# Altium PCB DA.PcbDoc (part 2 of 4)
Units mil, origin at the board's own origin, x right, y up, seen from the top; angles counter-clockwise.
Board outline 6588.03 x 5423.03 mil, 4 copper layers (Top Layer, GND, VCC, Bottom Layer); 506 components, 345 nets, 1676 pads, 350 vias.
Unrouted connection lines stored in the file: 30.
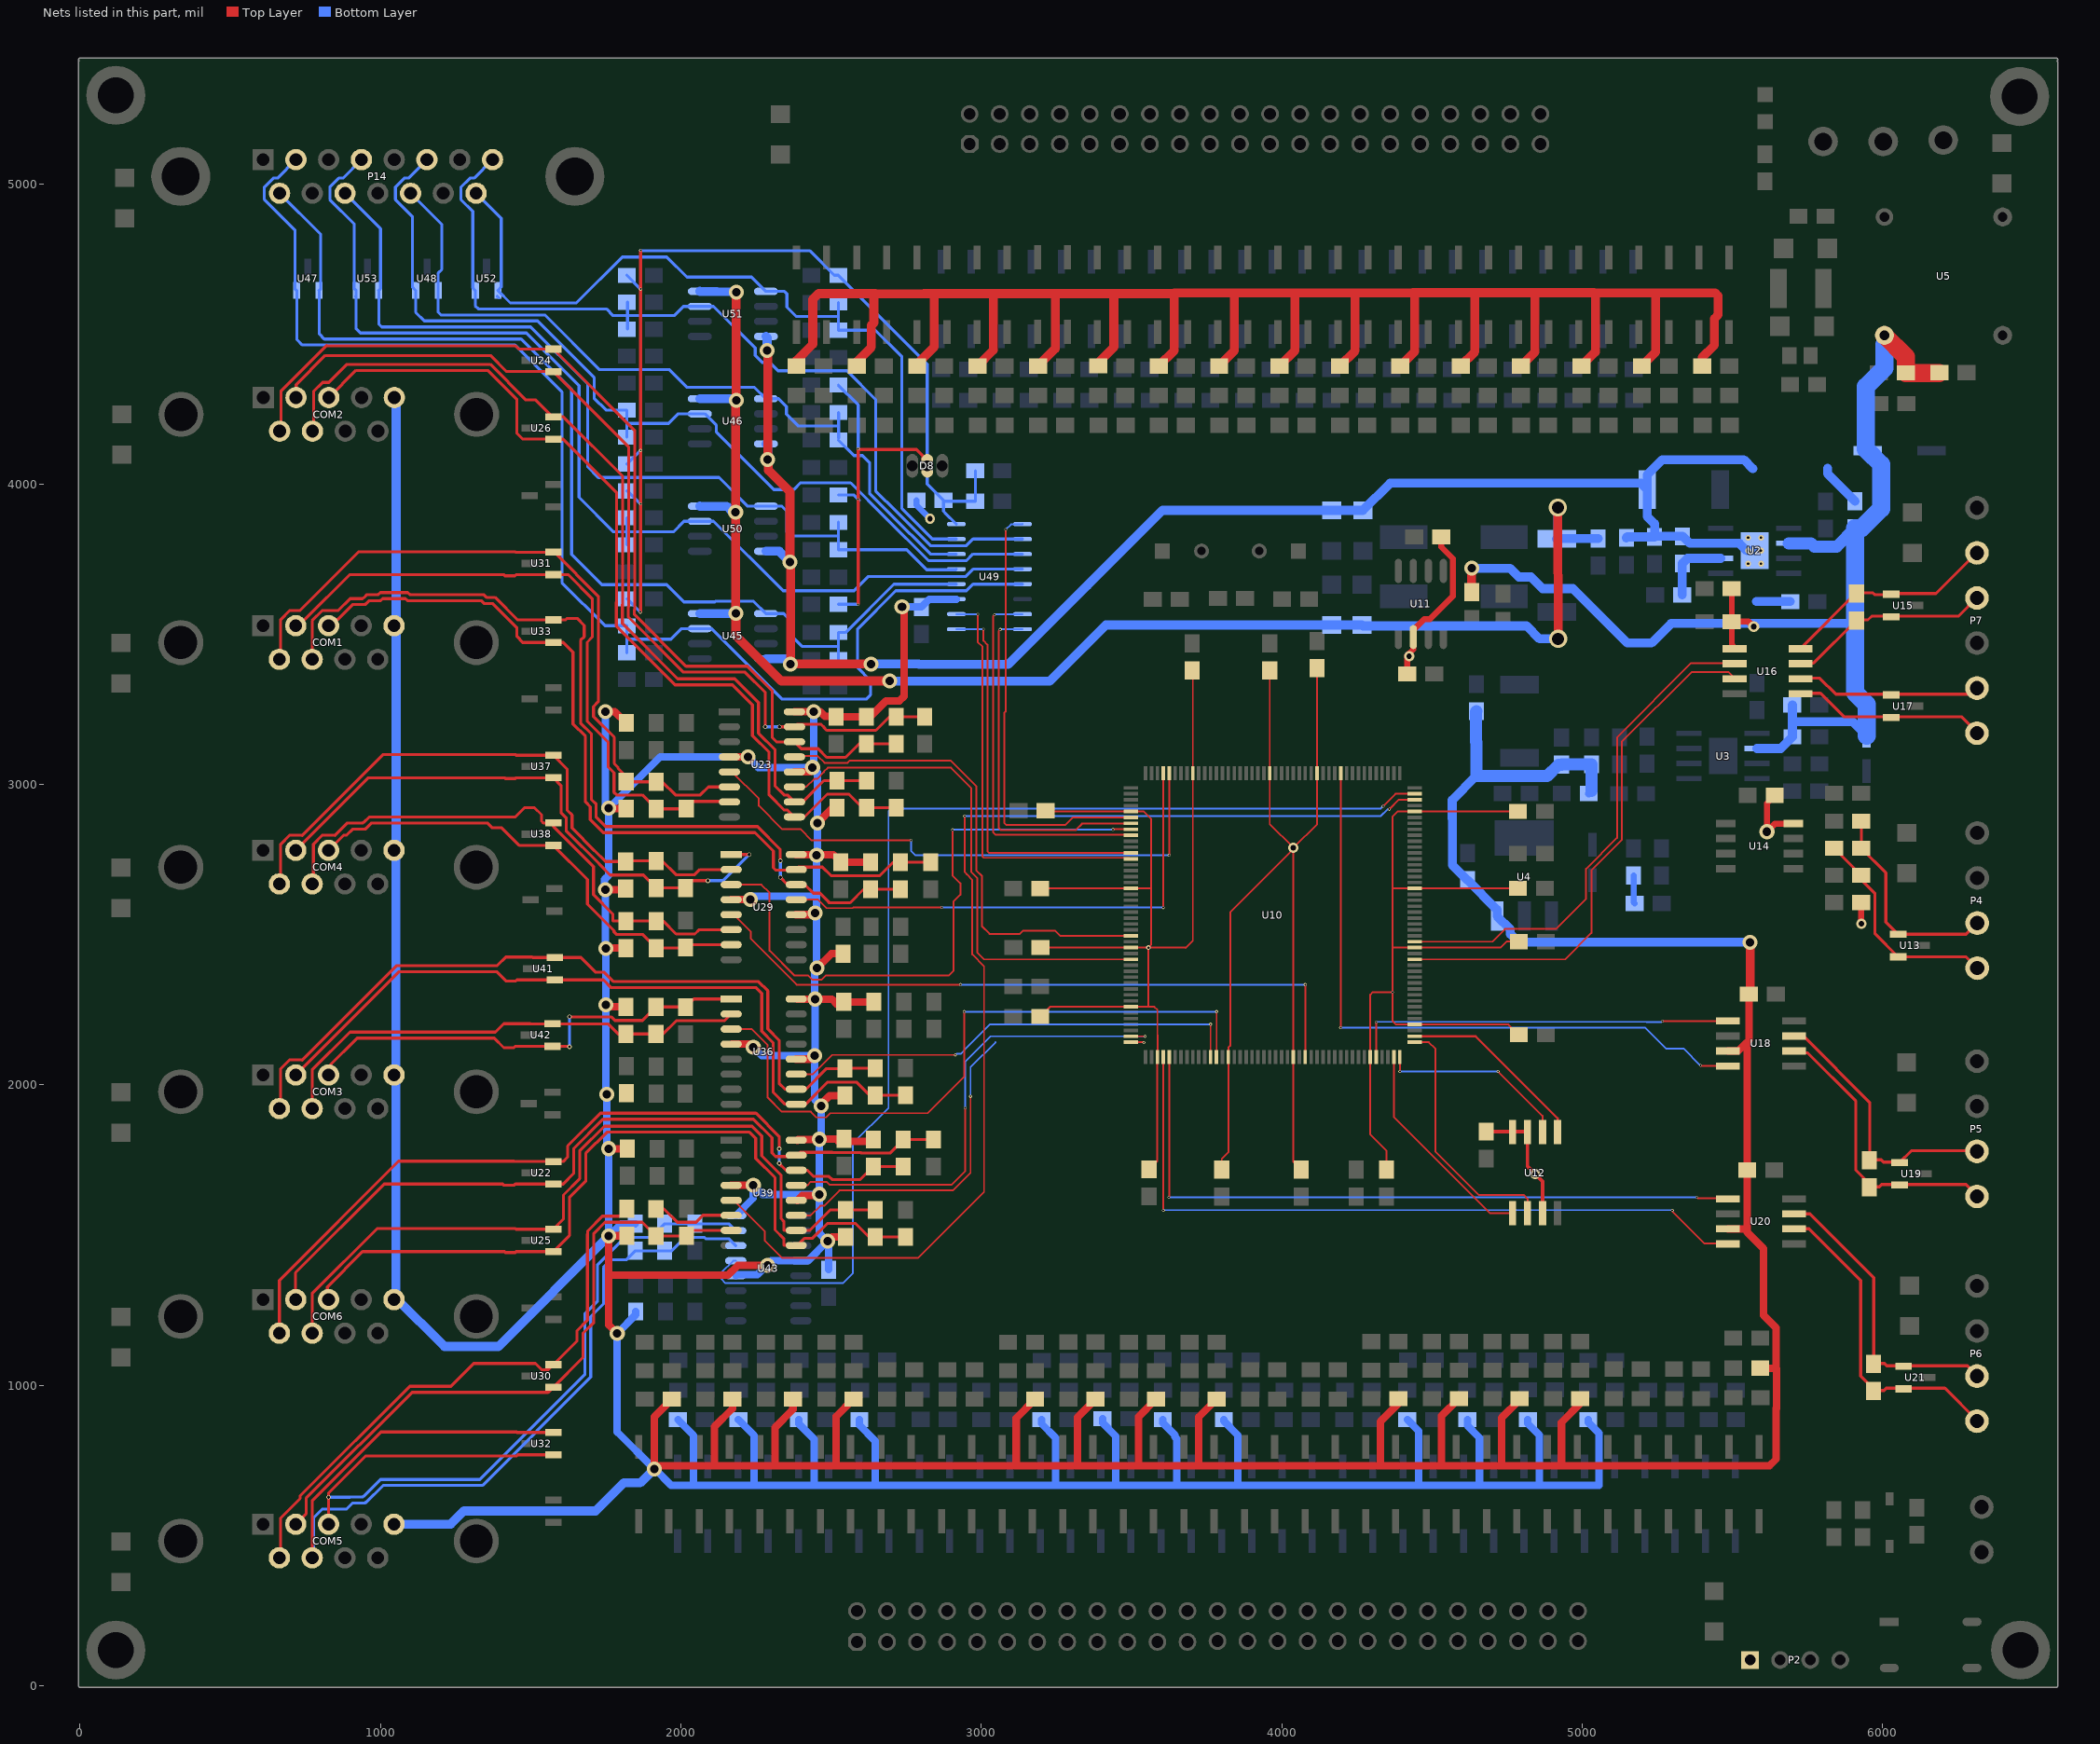
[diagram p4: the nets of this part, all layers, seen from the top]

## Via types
v1: diameter 10, hole 6, Top Layer to Bottom Layer, 112 vias
v2: diameter 50, hole 28, Top Layer to GND, 68 vias
v3: diameter 50, hole 28, Top Layer to Bottom Layer, 46 vias
v4: diameter 50, hole 28, GND to Bottom Layer, 36 vias
v5: diameter 15, hole 10, Top Layer to Bottom Layer, 28 vias
v6: diameter 60, hole 40, Top Layer to GND, 17 vias
v7: diameter 19.68, hole 7.87, Top Layer to Bottom Layer, 12 vias
v8: diameter 15, hole 8, Top Layer to GND, 8 vias
v9: diameter 60, hole 40, Top Layer to Bottom Layer, 7 vias
v10: diameter 34, hole 18, Top Layer to VCC, 4 vias
v11: diameter 10, hole 6, Top Layer to GND, 3 vias
v12: diameter 100, hole 60, Top Layer to Bottom Layer, 2 vias
v13: diameter 36, hole 20, Top Layer to VCC, 1 vias
v14: diameter 15, hole 8, Top Layer to VCC, 1 vias
v15: diameter 10, hole 6, Top Layer to VCC, 1 vias
v16: diameter 65, hole 40, Top Layer to Bottom Layer, 1 vias
v17: diameter 50, hole 28, Top Layer to VCC, 1 vias
v18: diameter 34, hole 18, VCC to Bottom Layer, 1 vias
v19: diameter 80, hole 50, Top Layer to Bottom Layer, 1 vias

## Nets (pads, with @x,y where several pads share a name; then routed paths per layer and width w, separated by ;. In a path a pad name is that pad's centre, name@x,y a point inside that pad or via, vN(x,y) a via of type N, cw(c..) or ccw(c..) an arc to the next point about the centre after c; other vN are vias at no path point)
3V3: C20.1 C25.1 C26.1 C34.2 C35.2 C36.2 C37.2 C38.2 C39.2 C40.2 C41.2 C42.2 C43.2 C44.2 C45.2 C46.2 C47.2 C48.2 C49.2 C50.1 C51.1 L2.2 P2.1 R15.2 R26.1 R90.1 U10.15 U10.23 U10.36 U10.49 U10.62 U10.72 U10.82 U10.91 U10.103 U10.114 U10.127 U10.136 U10.149 U10.159 U10.172 U11.2 U12.3 U12.7 U12.8 U14.8 U16.1 | length 12031.3
  Top Layer w6: C40.2@3196,2227.94 3228.51,2260.44 U10.82@3497.33,2260.44 3555,2260.44 ; C38.2@3196,2653.94 3196.21,2654.14 U10.62@3497.33,2654.14 3565,2654.14 ; C39.2@3197,2457.94 3197.64,2457.29 U10.72@3497.33,2457.29 v14(3556,2457.29) ; C37.2@3216.89,2910.05 U10.49@3497.33,2910.05 3540.95,2910.05 3565,2886 3565,2466.29 v14(3556,2457.29) ; C41.2@3558.06,1719 3585.91,1746.85 U10.91@3585.91,2093.12 3586.73,2093.93 3586.73,2166.27 3586,2167 3586,2250 3575.56,2260.44 3555,2260.44 ; C36.2@3701.94,3380 3704.02,3377.91 U10.36@3704.02,3038 3704,2480 3680,2456 3678.71,2457.29 v14(3556,2457.29) ; C42.2@3800.06,1718 3800.06,1754.06 3822.14,1776.14 U10.103@3822.14,2093.12 3822.14,2124.14 3828.27,2130.28 3828.27,2574.6 v10@4038.67,2785 ; C35.2@3959.93,3378.01 U10.23@3959.93,3038 3959.93,2868.41 v10(4038.67,2789.67) ; C43.2@4064.06,1718 4038.67,1743.39 U10.114@4038.67,2093.12 v10@4038.67,2785 ; C34.2@4117.41,3384 U10.15@4117.41,3038 4117.41,2868.41 v10(4038.67,2789.67) ; C44.2@4348.06,1718 4348.06,1781.94 4294.57,1835.43 U10.127@4294.57,2093.12 4294.57,2300.57 4303,2309 v15(4369,2309) ; 4369,2457.29 U10.149@4442.21,2457.29 4728.29,2457.29 4748.06,2477.06 C46.2@4789,2477.06 ; 4370,2654.14 U10.159@4442.21,2654.14 4785.92,2654.14 C47.2@4786,2654.06 ; C46.2@4785.23,2457.29 C46.2@4786,2458.06 ; C48.2@4785.98,2910.05 U10.172@4442.21,2910.05 U10.172@4442.21,2910.05 4385,2910 4369,2894 v15(4369,2309) ; C45.2@4789,2167.06 4754.68,2201.39 U10.136@4442.21,2201.39 4379.61,2201.39 4369,2212 v15(4369,2309) ; U12.7@4816,1845 U12.7@4818,1843 ; 3555,2260.44 3556,2261.44 v14(3556,2457.29) ; v10@4038.67,2785 v10(4038.67,2789.67)
  Top Layer w12: C25.1@4679.94,1845 U12.7@4816,1845 ; U12.7@4818,1843 4818,1729 4868.06,1678.94 U12.3@4868.06,1573
  Top Layer w20: C26.1@4418,3367.94 4418,3430 4438,3450 U11.2@4438,3491 4438,3514.25 4474.75,3551 4494,3551 4570,3627 4570,3752.25 4531,3791.25 R15.2@4531,3823.94 ; C50.1@5497,3542.06 C50.1@5498,3542.06 ; C51.1@5498,3654.06 C50.1@5498,3542.06 ; U16.1@5508,3454 5498,3464 C50.1@5498,3542.06 ; v13(5571,3525) 5553.94,3542.06 C50.1@5498,3542.06 ; C49.2@5641,2963.94 5615,2937.94 v17(5615,2843) 5642.06,2870.06 U14.8@5702.91,2870.06 ; v10(5929,2537) R26.1@5929,2607.06
  Bottom Layer w20: R90.1@2784,3946.06 2784,3930 v18(2829,3885) ; L2.2@5171,2697.27 5171,2608.06 C20.1@5175,2604.06
  other v10: 4843.03,1703.97 4424,3427
5V0: C16.2 C17.2 C18.1 C54.1 C57.1 C64.1 C65.1 C66.1 C67.1 C68.1 C69.2 COM1.5 COM2.5 COM3.5 COM4.5 COM5.5 COM6.5 L1.2 R7.2 R16.2 R30.1 R33.1 R36.1 R39.1 R42.1 R45.1 R48.1 R51.1 R54.1 R57.1 R60.1 R63.1 R66.1 R69.1 R72.1 R75.1 R78.1 R81.1 R117.2 R118.2 R119.2 R123.2 R124.2 R125.2 R129.2 R130.2 R131.2 R135.2 R136.2 R137.2 R141.2 R142.2 R143.2 R147.2 R148.2 R149.2 R153.2 R154.2 R155.2 R159.2 R160.2 R161.2 R177.2 R178.2 R183.2 R184.2 R191.2 R192.2 R197.2 R198.2 R202.2 R203.2 R207.2 R208.2 R212.2 R213.2 R217.2 R218.2 U4.3 U18.3 U20.3 U23.4 U23.12 U23.16 U29.4 U29.12 U29.16 U36.4 U36.12 U36.16 U39.4 U39.12 U39.16 U43.4 U43.12 U43.16 U49.3 | length 40069.3
  Top Layer w25: v3(1749,2650) 1812.2,2650 R48.1@1816.01,2653.81 ; v3(1749,3243) 1779.94,3243 R36.1@1817.94,3205 ; v3(1750,2455) 1750.56,2455.56 R51.1@1817.29,2455.56 ; v3(1753,1969) v3@1756,1972 ; v3@1757,2260 R60.1@1827.94,2260 ; v3(1760,1497) 1760,1367 ; v3(1760,1788) R72.1@1820.94,1788 ; v3@1761,2920 R39.1@1817.5,2920 ; v3@1767,1498 R75.1@1820.06,1498 ; v3(1788,1173) 1760,1201 1760,1367 ; R63.1@1818.06,1972 R63.1@1828.06,1972 ; R117.2@1970,953.94 1911,894.94 v3(1911,722) 1922.06,733.06 2112,733.06 ; U23.4@2161.5,3092 v3(2223,3092) ; U39.4@2167.23,1666 v3(2241,1666) ; U29.4@2167.23,2616.81 v3@2221.81,2616.81 ; U36.4@2170.99,2136 2231,2136 v3(2241,2126) ; R123.2@2171.45,953.94 2171.45,922.45 2112,863 2112,733.06 ; v3(2288,1399) 2189,1399 2157,1367 1760,1367 ; R129.2@2372.91,953.94 2372.91,919.91 2313,860 2313,733.06 ; U23.12@2378,3042 v3@2429,3042 ; U23.16@2378,3242 v3(2442,3242) 2463.46,3242 2478.96,3226.5 2515.36,3226.5 C64.1@2516.5,3225.36 R30.1@2617.27,3225.36 2629.56,3225.36 2682.06,3277.86 2726.86,3277.86 2742.5,3293.5 2742.5,3584.5 v3(2736,3591) ; U36.12@2383.73,2086 2433,2086 v3(2445,2098) ; U29.12@2383.73,2566.81 v3@2432.81,2566.81 ; U29.16@2383.73,2766.81 2506.85,2766.81 C65.1@2532.1,2741.56 2532.31,2741.35 R42.1@2630.88,2741.35 ; U39.12@2387.5,1616 2403.19,1631.69 2456.69,1631.69 v3(2461,1636) ; U39.16@2387.5,1816 2390.5,1819 v3(2461,1819) 2462.25,1820.25 C67.1@2522.19,1820.25 ; U36.16@2387.49,2286 v3(2447,2286) 2502.43,2286 C66.1@2521.43,2267 ; v3(2453,2389) 2500.81,2436.81 R45.1@2539.29,2436.81 ; v3(2454,2872) 2505,2923 R33.1@2519.06,2923 ; v3(2467,1930) 2467,1937 2494.5,1964.5 R57.1@2546.06,1964.5 ; v3(2488,1480) 2502.25,1494.25 R69.1@2548.31,1494.25 ; C67.1@2520.44,1816 2524.19,1812.25 R66.1@2619.19,1812.25 ; C66.1@2530.93,2276.5 C66.1@2541.93,2276.5 2630.5,2276.5 2630.93,2276.93 R54.1@2641.93,2276.93 ; R135.2@2574.36,953.94 2517,896.57 2517,733.06 ; R118.2@3178.73,953.94 3116,891.21 3116,733.06 ; R124.2@3380.18,953.94 3320,893.75 3320,733.06 ; R130.2@3581.64,953.94 3523,895.3 3523,735.06 3521,733.06 ; R136.2@3783.09,953.94 3724,894.85 3724,733.06 ; R119.2@4388.45,955.94 4388.45,940.45 4328,880 4328,733.06 ; R125.2@4589.91,955.94 4532,898.03 4532,733.06 ; R131.2@4791.36,955.94 4791.36,951.36 4732,892 4732,733.06 ; R137.2@4992.82,955.94 4992.82,938.82 4931,877 4931,733.06 ; U20.3@5485,1521 5549,1521 ; U18.3@5485,2113 5518.82,2113 5547.5,2141.68 5548.68,2141.68 ; C54.1@5555,2302.94 5555,2148 5548.68,2141.68 ; R16.2@5592.91,1057.38 5644.03,1057.38 5645.41,1056 ; 2112,733.06 2313,733.06 ; 2313,733.06 2517,733.06 ; 2517,733.06 3116,733.06 ; 3116,733.06 3320,733.06 ; 3320,733.06 3521,733.06 ; 3521,733.06 3724,733.06 ; 3724,733.06 4328,733.06 ; 4328,733.06 4532,733.06 ; 4532,733.06 4732,733.06 ; 4732,733.06 4931,733.06 ; 4931,733.06 5624.06,733.06 5646,755 5646,923.37 5646.41,923.78 5646.41,1055 5645.41,1056 ; 5548.68,2141.68 5548.68,1717.26 C57.1@5549,1716.94 5549,1521 ; 5549,1521 5549,1510 5604,1455 5604,1233.11 5645.41,1191.7 5645.41,1056
  Top Layer w30: R177.2@2384.59,4392.91 2384.59,4411.25 2439,4465.66 2439,4615 2458,4634 2647.09,4634 2647.55,4633.55 2808.24,4633.55 2808.69,4634 3040,4634 ; R183.2@2585.58,4407.58 2634,4456 2634,4529 2642,4537 2642,4628 ; R191.2@2786.57,4392.91 2786.57,4400.34 2843.45,4457.23 2843.45,4632 ; R197.2@2987.55,4392.91 2987.55,4393.27 3040,4445.71 3040,4634 ; R202.2@3188.54,4393.27 3246,4450.73 3246,4634 ; R207.2@3388,4394.06 3388,4403 3441.27,4456.27 3441.27,4633.73 3441,4634 ; R212.2@3590.52,4393.27 3642,4444.75 3642,4634 3441,4634 ; 3642,4636 3842,4636 ; R217.2@3791.51,4393.27 3842,4443.76 3842,4636 ; R178.2@3992.49,4393.27 4044,4444.78 4044,4636 ; R184.2@4193.48,4393.27 4244,4443.79 4244,4636 ; R192.2@4394.47,4393.27 4442,4440.8 4442,4632 ; 4436,4638 5039,4638 5041,4636 ; R198.2@4595.46,4393.27 4642.91,4440.72 4642.91,4636 ; R203.2@4796.44,4393.27 4843,4439.82 4843,4632 4839,4636 ; R208.2@4997.43,4393.27 5044,4439.84 5044,4633 5041,4636 ; R213.2@5198.42,4393.27 5244,4438.85 5244,4634 5242,4636 ; R218.2@5399.41,4392.91 5399.41,4421.98 5440,4462.57 5440,4551 5452,4563 5452,4627 5443,4636 5242,4636 ; C54.1@5555,2302.94 5559,2306.94 v3(5559,2475) ; 3040,4634 3246,4634 ; 3246,4634 3441,4634 ; 3842,4636 4044,4636 ; 4044,4636 4244,4636 ; 4244,4636 4642.91,4636 ; 4642.91,4636 4839,4636 ; 4839,4636 5041,4636 ; 5041,4636 5242,4636
  Bottom Layer w25: v3(1749,3243) 1749,2932 v3(1760,2921) ; R78.1@1848.06,1538 1801,1538 v3(1760,1497) v3(1760,1788) 1753,1795 v3(1753,1969) 1750,1972 v3(1750,2267) v3(1750,2455) 1749,2456 v3(1749,2650) 1746,2653 1746,2684 1760,2698 v3(1760,2921) ; R81.1@1849.94,1246 1849.94,1234.94 v3(1788,1173) 1788,845 v3(1911,722) ; v3@1912.12,723.12 1967.68,667.56 2045.5,667.56 ; R141.2@1990,886 2042,834 2042,673.06 2041,672.06 2045.5,667.56 ; U43.12@2182.5,1365.69 2184.81,1368 2254,1368 2301,1415 U43.4@2399,1415 2423,1415 v3(2488,1480) ; U43.16@2182.5,1565 2241,1623.5 v3(2241,1666) 2271,1636 v3(2461,1636) ; R147.2@2191.28,886 2244,833.28 2244,669.06 ; v3(2231,2617) 2242,2628 2451.92,2628 ; v3(2241,2126) 2269,2098 v3(2445,2098) 2445,1952 v3(2467,1930) 2467,1825 v3(2461,1819) v3(2461,1636) ; R153.2@2392.56,886 2392.56,872.51 2444,821.06 2444,668.06 ; v3(2442,3242) 2442,3061 v3(2438,3057) ; v3@2445,2286 2445,2381 v3(2453,2389) ; v3@2447,2100 v3(2447,2286) ; v3@2451.92,2390.08 2451.92,2628 ; C68.1@2491.06,1385 2491.06,1476.94 v3(2488,1480) ; R159.2@2593.83,886 2593.83,868.23 2647,815.06 2647,669.06 ; v3(2736,3591) C69.2@2800.94,3591 2826.94,3617 U49.3@2916.76,3617 ; R142.2@3200,886 3200,873.06 3247,826.06 3247,667.56 ; R148.2@3403.35,889.29 3403.35,874.71 3447,831.06 3447,668.06 ; R154.2@3604,886 3604,875.06 3644,835.06 3644,829 3651,822 3651,667.56 3247,667.56 ; R160.2@3807,886 3807,881.06 3854,834.06 3854,675.56 3846,667.56 ; R143.2@4418,886 4456,848 4456,669.06 ; R149.2@4618,886 4618,866.06 4658,826.06 4658,667.56 ; 4653.81,3211.19 L1.2@4653.81,3228 ; R155.2@4819,886 4819,873.06 4857,835.06 4857,667.56 ; C16.2@4930.88,3066 C16.2@4931.88,3067 ; R161.2@5020,886 5020,877.06 5056,841.06 5056,667.56 4857,667.56 ; R7.2@5021.81,2970.06 R7.2@5030.88,2979.13 ; v3(1760,2921) 1931,3092 v3(2223,3092) 2258,3057 v3(2438,3057) ; 2045.5,667.56 3247,667.56 ; v3(2438,3057) 2454,3041 v3(2454,2872) 2454,2767.08 v3(2451.92,2765) 2451.92,2628 ; v3(2461,1636) 2461,1507 v3(2488,1480) ; 3247,667.56 3846,667.56 ; 3846,667.56 4658,667.56 ; 4658,667.56 4857,667.56
  Bottom Layer w30: COM5.5@1045.11,537.91 1233.41,537.91 1277.51,582 1716,582 1809.64,675.64 1864.64,675.64 v3(1911,722) ; COM2.5@1046.11,4287.91 1052.09,4281.92 1052.09,2787.89 COM4.5@1045.11,2780.91 1051.09,2774.92 1051.09,1291.56 1212.98,1129.67 1392.67,1129.67 v3(1760,1497) ; 4567.94,2812.36 4567.94,2731.64 4617.58,2682 C18.1@4617.94,2682 4716.9,2583.04 U4.3@4716.9,2562.13 4760.8,2518.23 4760.8,2502.56 4788.35,2475 v3(5559,2475) ; 4568,2819.89 4568,2886 4567,2887 4567,2948 4647.02,3028.02
  Bottom Layer w40: 4646,3142 4646,3242 L1.2@4648,3244 ; 4648,3142 4648,3029 4647.02,3028.02 4883.02,3028.02 4921,3066 C16.2@4930.88,3066 ; C16.2@4931.88,3067 C17.2@5030.88,3067 R7.2@5030.88,2979.13
  other v3: 2447,2572
12V0: C1.1 C2.1 D1.2 R1.1 U45.8 U46.8 U50.8 U51.8 | length 5211.8
  Top Layer w30: v3(2184,4639) v3(2184,4279) 2182,4277 v3(2182,3907) 2182,3571 v3(2183,3570) 2183,3496 2334,3345 2687,3345 v3@2695,3337 ; v9@4919,3915 v9(4920,3485)
  Bottom Layer w30: U45.8@2063,3568.89 v3@2184,3568.89 ; U50.8@2063,3926.44 2063.44,3926 2153,3926 2172,3907 v3(2182,3907) ; U46.8@2063,4284 2179,4284 v3(2184,4279) ; U51.8@2063,4641.56 v3(2184,4639) ; v3@2695,3336 2703,3344 3227.57,3344 3414.57,3531 C1.1@4166,3531 C2.1@4267,3531 4270,3528 4815,3528 4858,3485 v9(4920,3485) ; D1.2@4915,3817.65 D1.2@4916.35,3819 ; v9(4919,3922) 4919,3821.65 D1.2@4916.35,3819 ; R1.1@5053.06,3819 D1.2@4916.35,3819
  other v3: 2695,3345
24V0: C4.1 C5.2 C12.1 C15.2 C21.2 C23.2 R6.2 R12.2 U2.2 U3.2 U5.3 | length 3922.8
  Top Layer w30: v3(4632,3720) 4632.06,3719.94 R12.2@4632.06,3640
  Top Layer w60: U5.3@6006,4495.3 6077,4424.3 C23.2@6077,4369.94 C21.2@6187.87,4369.94
  Bottom Layer w30: v3(4632,3720) 4760,3720 4789.06,3690.94 4829.42,3690.94 4868.36,3652 4969,3652 5150,3471 5230.78,3471 5295.78,3536 5908.06,3536 ; U3.2@5582,3120 5660.88,3120 R6.2@5699.81,3158.94 5699.81,3207 ; C15.2@5699.81,3264.94 5699.81,3207 ; C12.1@5946.81,3163 5900.88,3208.94 5701.75,3208.94 5699.81,3207
  Bottom Layer w40: U2.2@5687.19,3803 5761.51,3803 5772.51,3792 5847.36,3792 C5.2@5908.06,3852.7
  Bottom Layer w60: C5.2@5908.06,3853 C5.2@5908.06,3852.7 ; C12.1@5946.81,3163 5946.81,3267.19 5908.06,3305.94 5908.06,3536 C5.2@5908.06,3852.7 ; U5.3@6006,4465 6006,4386 5944,4324 5944,4116.7 C4.1@5949.7,4111 5995,4065.7 5995,3918.37 5929.33,3852.7 C5.2@5908.06,3852.7
422_A: P7.2 R27.1 U15.1 U16.8 | length 724.1
  Top Layer w10: U16.8@5728,3454 5912,3638 5913.94,3638 5967,3638 5973,3632 6026.23,3632 6029.63,3635.4 6177.4,3635.4 P7.2@6315,3773
422_B: P7.3 R27.2 U15.2 U16.7 | length 677.7
  Top Layer w10: U16.7@5728,3404 5769.94,3404 5913.94,3548 5951,3548 5963.6,3560.6 6029.63,3560.6 6252.6,3560.6 P7.3@6315,3623
422_DI: U10.147 U16.3 | length 1784.3
  Top Layer w6: U10.147@4442.21,2417.92 4727.3,2417.92 4727.38,2418 4943,2418 5031,2506 5031,2714.75 5131.82,2815.57 5131.82,3141.82 5365,3375 5487,3375 U16.3@5508,3354
422_RO: U10.150 U16.2 | length 1704
  Top Layer w6: U10.150@4442.21,2476.98 4700.98,2476.98 4743,2519 4912,2519 5013,2620 5013,2719.37 5115.82,2822.2 5115.82,3156.82 5363,3404 U16.2@5508,3404
422_Y: P7.6 U16.5 U17.2 | length 641.3
  Top Layer w10: U16.5@5728,3304 5793,3304 5871.4,3225.6 6029.63,3225.6 6262.4,3225.6 P7.6@6315,3173
422_Z: P7.5 U16.6 U17.1 | length 618.6
  Top Layer w10: U16.6@5728,3354 5791,3354 5844.6,3300.4 6029.63,3300.4 6292.4,3300.4 P7.5@6315,3323
-12V0: C5.1 C6.1 C7.1 C8.2 C9.2 D2.1 R3.2 R4.1 U2.7 U2.9 U45.4 U46.4 U50.4 U51.4 | length 5762.9
  Top Layer w30: v3(2289,4082) v3@2289,4444 ; v3@2291,4069 2291,4046 2363,3974 v3(2363,3741) 2365,3739 v3(2365,3401) v3(2633,3401)
  Bottom Layer w10: 5579,3609 5579.06,3609.06
  Bottom Layer w30: U45.4@2283,3418.89 2347.11,3418.89 v3(2365,3401) ; U50.4@2283,3776.44 2327.56,3776.44 v3(2363,3741) ; U46.4@2283,4134 2289,4128 v3(2289,4082) ; U51.4@2283,4491.56 2287,4487.56 v3(2287,4445) ; v3@2640,3401 2791,3401 2792,3400 3089.94,3400 3353,3663.06 3353.06,3663.06 3602.65,3912.65 C8.2@4166,3912.65 C9.2@4270,3912.65 4360.35,4003 5195.35,4003 D2.1@5216.35,3982 ; R3.2@5146.94,3821 5149.94,3824 C6.1@5241.06,3824 ; 5568,4051 5538,4081 5267,4081 5216.35,4030.35 D2.1@5216.35,3982 ; U2.9@5574,3778 v7(5552.35,3778) 5548,3778 5523,3803 U2.7@5460.81,3803 5358.06,3803 5334.06,3827 5244.06,3827 C6.1@5241.06,3824 ; 5579.06,3609.06 R4.1@5693,3609.06 ; 5817,4052 5817,4034.06 C5.1@5908.06,3943 ; D2.1@5216.35,3982 5216.35,3892.65 5241.06,3867.94 C6.1@5241.06,3824
  other v7: 5552.35,3734.69 5595.65,3734.69 5595.65,3778 5552.35,3821.31 5595.65,3821.31
A: P4.4 R24.1 R25.2 U13.2 | length 728.4
  Top Layer w10: R24.1@5839,2787.94 R25.2@5929,2697.94 5929,2683.28 5974,2638.28 5974,2504.23 U13.2@6051.63,2426.6 6277.4,2426.6 P4.4@6315,2389
A0: U10.70 U23.13 | length 1646.3
  Top Layer w6: U23.13@2378,3092 2381,3095 2455.19,3095 2477.83,3072.36 2555.17,3072.36 2562.81,3080 2898,3080 2925.23,3052.77 2925.23,3052.4 2983,2994.63 2983,2714.63 3002,2695.63 3002,2528 3027,2503 3128.02,2503 3138.96,2513.94 3245.04,2513.94 3262.33,2496.65 U10.70@3497.31,2496.65
A0_N: COM2.2 R31.2 R32.1 U23.15 U24.1 | length 3119
  Top Layer w10: COM2.2@718.94,4287.91 718.94,4330.94 816,4428 1366.33,4428 1419.73,4374.6 U24.1@1575.37,4374.6 1826,4123.97 1826,3591.57 1825,3590.57 1825,3557.43 2008.43,3374 2213,3374 2281,3306 v5(2281,3192) ; v5(2328,3192) U23.15@2378,3192 2386.65,3200.65 2465.92,3200.65 2476.5,3190.07 2476.5,3189.14 2485.29,3180.36 2648.48,3180.36 2693.48,3225.36 R31.2@2716.38,3225.36 R32.1@2811.5,3225.36
  Bottom Layer w10: v5(2281,3192) v5(2328,3192)
A0_P: COM2.6 R30.2 R31.1 U23.14 U24.2 | length 3283.2
  Top Layer w10: COM2.6@664.34,4176.09 668.51,4180.27 668.51,4308.8 820.72,4461 821.72,4460 1449.57,4460 1460.17,4449.4 U24.2@1575.37,4449.4 1846,4178.77 1846,3583.28 1845,3582.28 1845,3565.72 2016.72,3394 2221.28,3394 2304,3311.28 2304,3156 2318,3142 U23.14@2378,3142 2401.19,3118.81 2456.84,3118.81 2485.29,3090.36 2547.72,3090.36 2592.72,3135.36 R30.2@2617.27,3135.36 R31.1@2716.38,3135.36
A1: U10.40 U23.5 | length 1886.2
  Top Layer w6: U23.5@2161.5,3042 2170.21,3042 2259.23,2952.98 2259.23,2929.43 2337.66,2851 2398.63,2851 2435.63,2814 v1(2766,2814) ; v1(3625,2764.65) 3625.28,2764.93 U10.40@3625.28,3038
  Bottom Layer w6: v1(2766,2814) 2766,2779 2780,2765 3624.65,2765 v1(3625,2764.65)
A1_N: COM1.2 R40.2 R41.1 U23.7 U31.1 | length 2165.3
  Top Layer w10: 749.05,3550.23 897.36,3698.54 1410.89,3698.54 1414.43,3695 1447.57,3695 1451.11,3698.54 U31.1@1575.37,3698.54 1625.18,3698.54 1705,3618.72 1705,3490.72 1688,3473.72 1688,3211 1757.94,3141.06 1757.94,3058.78 1777.5,3039.21 1777.5,2973.79 1786.29,2965 1871.5,2965 R40.2@1917.5,2919 2016.63,2919 R41.1@2017.63,2920 ; R41.1@2012.63,2920 R41.1@2017.63,2920 ; U23.7@2161.5,2942 2159.5,2944 2041.63,2944 R41.1@2017.63,2920
A1_P: COM1.6 R39.2 R40.1 U23.6 U31.2 | length 2394.6
  Top Layer w10: COM1.6@663.34,3416.76 667.51,3420.93 667.51,3549.46 697.05,3579.01 732,3579.01 927.99,3775 1447.57,3775 1449.23,3773.34 U31.2@1575.37,3773.34 1578.66,3773.34 1725,3627 1725,3275.57 1709,3259.57 1709,3226.43 1777.94,3157.5 1777.94,3070 1790.5,3057.44 1790.5,3054.5 R39.2@1836,3009 ; R39.2@1820.63,3010 1821.63,3009 R39.2@1836,3009 ; U23.6@2161.5,2992 2091.5,2992 2064.5,2965 1981.41,2965 1937.41,3009 R40.1@1917.5,3009 R39.2@1836,3009
A2: U10.52 U29.3 | length 2078.5
  Top Layer w6: U29.3@2167.23,2666.81 2268.19,2666.81 2295,2640 2295,2446.83 2376.83,2365 2423.26,2365 2437.26,2351 2468.74,2351 2482.74,2365 2892,2365 2908,2381 2908,2611.26 2930,2633.26 2930,2671 2904,2697 v1(2904,2849) ; v1(3438,2850.65) 3438.35,2850.99 U10.52@3497.33,2850.99
  Bottom Layer w6: v1@2904,2850.65 v1(3438,2850.65)
A2_N: COM4.2 R49.2 R50.1 U29.1 U37.1 | length 1961.4
  Top Layer w10: COM4.2@708,2770.96 COM4.2@717.94,2780.91 959.52,3022.48 1412.95,3022.48 1415.43,3020 1448.57,3020 1451.05,3022.48 U37.1@1575.37,3022.48 1601,2996.85 1601,2906.88 1617.93,2889.95 1617.93,2846.35 1729,2735.28 1729,2734 1764.19,2698.81 1874.89,2698.81 R49.2@1917.89,2655.81 R50.1@2014.01,2655.81 ; R50.1@2015.01,2654.81 2040.01,2679.81 v5(2090.19,2679.81) ; U29.1@2167.23,2766.81 2226.81,2766.81 v5(2227,2767)
  Bottom Layer w10: v5(2090.19,2679.81) 2139.81,2679.81 v5(2227,2767)
A2_P: COM4.6 R48.2 R49.1 U29.2 U37.2 | length 2035.2
  Top Layer w10: COM4.6@663.34,2669.09 667.51,2673.27 667.51,2801.8 697.05,2831.34 738.83,2831.34 739.46,2830.71 1008.76,3100 1448.57,3100 1451.29,3097.28 U37.2@1575.37,3097.28 1621,3051.65 1621,2915.17 1637.93,2898.24 1637.93,2854.79 1712.72,2780 1713,2780 1749.19,2743.81 R48.2@1816.01,2743.81 ; R48.2@1818.01,2745.81 R49.1@1917.89,2745.81 1937.8,2745.81 1983.8,2699.81 2046.23,2699.81 2063.23,2716.81 U29.2@2167.23,2716.81
A3: U10.100 U36.11 | length 1553.9
  Top Layer w6: U36.11@2387.49,2036 2439,2036 2503,2100 v1(2914,2100) ; U10.100@3763,2093.2 v1(3763,2202)
  Bottom Layer w6: v1(2914,2100) 2917.5,2103.5 2931.96,2103.5 2942.5,2114.04 2942.5,2115.5 3029,2202 v1(3763,2202)
A3_N: COM3.2 R58.2 R59.1 U36.9 U41.1 | length 2558.4
  Top Layer w10: COM3.2@717.94,2033.24 1061.71,2377 1386.43,2377 1417.43,2346 1450.57,2346 1454.17,2349.6 U41.1@1580.37,2349.6 1742.26,2349.6 1767.86,2324 2250.15,2324 2269,2305.15 2269,2178.46 2307,2140.46 2307,1976 2347,1936 U36.9@2383.73,1936 2415,1936 2488.5,2009.5 2584.5,2009.5 R58.2@2628,1966 ; R58.2@2646.93,1965.5 2747.56,1965.5 R59.1@2748.06,1966
A3_P: COM3.6 R57.2 R58.1 U36.10 U41.2 | length 2627
  Top Layer w10: COM3.6@663.34,1921.43 667.51,1925.6 667.51,2054.13 697.05,2083.67 738.83,2083.67 739.46,2083.04 1053.21,2396.79 ; 1053,2397 1388.43,2397 1417.43,2426 1505.06,2426 1506.65,2424.4 U41.2@1580.37,2424.4 1667.46,2424.4 1716.86,2375 1745.15,2375 1776.15,2344 2258.43,2344 2289,2313.43 2289,2186.74 2327,2148.74 2327,2005 2346,1986 U36.10@2383.73,1986 2416,1986 2484.5,2054.5 2535.06,2054.5 2536.06,2055.5 R58.1@2635.93,2055.5
A4: U10.87 U39.13 | length 1632.7
  Top Layer w6: U39.13@2387.5,1666 2421,1666 2432.43,1677.43 2485.11,1677.43 2495.29,1667.25 2900.99,1667.25 2946,1712.26 v1(2946,1924) ; U10.87@3497.33,2162.02 v1(3544.98,2162.02)
  Bottom Layer w6: v1(2946,1924) 2946,2077 3031.02,2162.02 v1(3544.98,2162.02)
A4_N: COM6.2 R67.2 R68.1 U22.1 U39.15 | length 2580
  Top Layer w10: COM6.2@717.94,1285.57 717,1286.52 717,1375 1012.36,1670.36 1407.07,1670.36 1411.43,1666 1444.57,1666 1448.93,1670.36 U22.1@1575.37,1670.36 1608,1670.36 1643,1705.36 1643,1788.57 1740.43,1886 2241.57,1886 2303,1824.57 2303,1773.72 2314.72,1762 2379.73,1762 U39.15@2383.73,1766 ; U39.15@2387.5,1766 2397.5,1776 2503.16,1776 2503.91,1775.25 2598.97,1775.25 2600.97,1773.25 2695.31,1773.25 R67.2@2740.31,1818.25 R68.1@2840.19,1818.25
A4_P: COM6.6 R66.2 R67.1 U22.2 U39.14 | length 2662.6
  Top Layer w10: COM6.6@663.34,1173.76 663.34,1349.62 1059.72,1746 1444.57,1746 1445.4,1745.17 U22.2@1575.37,1745.17 1608,1745.17 1623,1760.17 1623,1796.85 1732.15,1906 2249.85,1906 2327,1828.85 v5(2327,1787) ; v5(2327,1739) 2350,1716 U39.14@2383.73,1716 ; U39.14@2387.5,1716 2421.43,1716 2442,1695.43 2492.57,1695.43 2502.75,1685.25 2597.19,1685.25 R66.2@2640.19,1728.25 R67.1@2740.31,1728.25
  Bottom Layer w10: v5@2327,1740 v5(2327,1787)
A5: U10.174 U39.5 | length 3829.4
  Top Layer w6: U39.5@2167.23,1616 2175.94,1616 2279.29,1512.64 2279.29,1481.62 2336.92,1424 2789,1424 3009,1644 3009,2395.37 2970,2434.37 2970,2682.37 2951,2701.37 2951,2702 2944,2709 v1(2944,2895) ; v1@4357.82,2917.82 4389.42,2949.42 U10.174@4442.21,2949.42
  Bottom Layer w6: v1(2944,2895) 4329.81,2895 4352.46,2917.65 v1(4358,2917.65)
A5_N: COM5.2 R76.2 R77.1 U30.1 U39.7 | length 2143.4
  Top Layer w10: COM5.2@717.94,537.91 752.47,572.43 752.47,624.04 1105.43,977 1558.07,977 U30.1@1575.37,994.3 1674,1092.93 1674,1173.59 1710,1209.59 1710,1506 1747,1543 1871.19,1543 R76.2@1916.94,1497.25 2018.31,1497.25 R77.1@2019.06,1498 2037.06,1516 U39.7@2167.23,1516
A5_P: COM5.6 R75.2 R76.1 U30.2 U39.6 | length 2207.5
  Top Layer w10: COM5.6@663.34,426.09 667.51,430.27 667.51,558.8 732.47,623.76 732.47,632.32 1097.15,997 1234.24,997 1310.24,1073 1515.92,1073 1536.92,1052 1558.26,1052 U30.2@1575.37,1069.11 1654,1147.74 1654,1181.87 1689,1216.87 1689,1503.07 1690,1504.07 1690,1514.28 1738.72,1563 1795.06,1563 R75.2@1820.06,1588 ; R76.1@1916.94,1587.25 1943.6,1587.25 1987.85,1543 2050.28,1543 2073.28,1566 U39.6@2167.23,1566
AO0: P14.9 R86.1 R92.2 U45.1 U47.1 U49.4 | length 3587
  Bottom Layer w10: P14.9@663.83,4968.09 801,4830.93 801,4650.23 U47.1@795.4,4644.63 796.4,4643.63 796.4,4499.6 813,4483 1468,4483 1636,4315 1636,3766 1737,3665 1953,3665 2010,3608 2112.3,3608 2114.3,3610 2241.89,3610 U45.1@2283,3568.89 2342.11,3568.89 2361,3550 2361,3502 2403,3460 2524,3460 ; R86.1@2524,3416.17 2524,3460 ; U49.4@2916.76,3667 2708.72,3667 2547.78,3506.06 R92.2@2524,3506.06 2524,3460
AO1: P14.2 R95.1 R99.2 U45.7 U47.2 U49.13 | length 4427.3
  Bottom Layer w10: P14.2@718.31,5079.91 656.93,5018.53 642.94,5018.53 613.4,4988.98 613.4,4947.2 715,4845.61 715,4650.23 U47.2@720.6,4644.63 721.6,4643.63 721.6,4481.4 740,4463 1448,4463 1604,4307 1604,3672 1747.58,3528.42 R99.2@1820,3528.42 1820,3483.55 ; R95.1@1820,3438.69 1820,3483.55 ; U49.13@3137.24,3667 2972.33,3667 2950.44,3645.11 2715.11,3645.11 2588,3518 2588,3389 2631,3346 2631,3298 2617,3284 2337,3284 2102.11,3518.89 U45.7@2063,3518.89 2001.89,3518.89 1967,3484 1820.45,3484 1820,3483.55
AO2: P14.11 R103.1 R107.2 U49.5 U50.1 U53.1 | length 3024.3
  Bottom Layer w10: P14.11@881.95,4968.09 1000,4850.04 1000,4650.9 U53.1@993.73,4644.63 994.73,4643.63 994.73,4532.27 1004,4523 1500,4523 1690,4333 1690,4057 1725,4022 2127,4022 2222.56,3926.44 U50.1@2283,3926.44 2336.56,3926.44 2353,3910 2353,3840 2366,3827 2524,3827 ; R107.2@2524,3872.88 2524,3827 ; U49.5@2916.76,3717 2914.76,3715 2818,3715 2751.47,3781.53 R103.1@2524,3781.53 2524,3827
AO3: P14.4 R111.1 R115.2 U49.12 U50.7 U53.2 | length 3598
  Bottom Layer w10: U53.2@916.93,4625.63 U53.2@918.93,4623.63 ; U53.2@919,4623.56 U53.2@918.93,4623.63 ; P14.4@936.46,5079.91 875.08,5018.53 861.05,5018.53 831.51,4988.98 831.51,4947.2 912,4866.72 912,4651.56 U53.2@918.93,4644.63 U53.2@918.93,4623.63 ; R111.1@1820,3797.62 1820,3841 ; R115.2@1820,3887.35 1820,3841 ; 1822,3841 1975,3841 2010.15,3876.15 2062.7,3876.15 U50.7@2063,3876.44 2108.56,3876.44 2340,3645 2576,3645 2623,3692 2947.33,3692 2972.33,3717 U49.12@3137.24,3717 ; U53.2@918.93,4623.63 918.93,4517.07 933,4503 1486,4503 1661,4328 1661,3956 1776,3841 1820,3841
AO4: P14.13 R87.1 R91.2 U46.1 U48.1 U49.6 | length 2644.6
  Bottom Layer w10: P14.13@1100.06,4968.09 1204,4864.15 1204,4714.42 1192.07,4702.49 U48.1@1192.07,4644.63 1192.07,4571.93 1201,4563 1547,4563 1729,4381 1962,4381 2021,4322 2245,4322 U46.1@2283,4284 2325,4284 2351,4258 2351,4233 2391,4193 2525,4193 ; R87.1@2524,4146.9 2575.9,4095 2604.57,4095 2628,4071.57 2628,3969.28 2699,3898.28 2830.28,3767 U49.6@2916.76,3767 ; R91.2@2524,4238.24 2525,4237.24 2525,4193 ; R87.1@2525,4152.82 2525,4193
AO5: P14.6 R96.1 R100.2 U46.7 U48.2 U49.11 | length 3129.5
  Bottom Layer w10: P14.6@1154.62,5079.91 1093.24,5018.53 1079.17,5018.53 1049.62,4988.98 1049.62,4947.2 1106,4890.83 1106,4655.9 U48.2@1117.27,4644.63 1117.27,4571.73 1146,4543 1523,4543 1711,4355 1711,4286 1750.71,4246.29 R96.1@1820,4246.29 1820,4203 ; R100.2@1820,4156.55 1820,4203 ; U49.11@3137.24,3767 2972.33,3767 2950.44,3745.11 2823.89,3745.11 2679,3890 2564.78,4004.22 2397.79,4004.22 2375.57,3982 2309,3982 2118,4173 2118,4195.18 2079.18,4234 U46.7@2063,4234 1991,4234 1959,4202 1821,4202 1820,4203
AO6: P14.15 R104.1 R108.2 U49.7 U51.1 U52.1 | length 2761
  Bottom Layer w10: P14.15@1318.17,4968.09 1402,4884.26 1402,4656.23 U52.1@1390.4,4644.63 1432.03,4603 1651.83,4603 1804.83,4756 1953,4756 2020,4689 2235.56,4689 U51.1@2283,4641.56 2344.44,4641.56 2353,4633 2353,4589 2384.06,4557.94 2524,4557.94 ; U52.1@1388.4,4625.63 U52.1@1394.03,4620 ; R108.2@2524,4603.61 2524,4557.94 ; U49.7@2916.76,3817 2836.85,3817 2739,3914.85 2735.31,3918.54 2735.31,4423.69 2646.73,4512.27 R104.1@2524,4512.27 2524,4557.94
AO7: P14.8 R112.1 R116.2 U49.10 U51.7 U52.2 | length 3027.4
  Bottom Layer w10: P14.8@1372.77,5079.91 1311.39,5018.53 1297.28,5018.53 1267.73,4988.98 1267.73,4947.2 1307,4907.94 1307,4653.23 U52.2@1315.6,4644.63 1315.6,4593.4 1326,4583 1752,4583 1774.11,4560.89 1822,4560.89 ; R112.1@1822,4515.95 1822,4560.89 ; R116.2@1822,4605.82 1822,4560.89 ; U49.10@3137.24,3817 2972.33,3817 2950.44,3795.11 2830.46,3795.11 2719,3906.57 2648,3977.57 2648,4281.8 2552.8,4377 2323,4377 2295,4405 2270.43,4405 2247,4428.43 2247,4453 2108.44,4591.56 U51.7@2063,4591.56 2008.67,4591.56 1978,4560.89 1822,4560.89
B: P4.3 R23.2 R24.2 U13.1 | length 706.3
  Top Layer w10: R23.2@5929,2877.94 R24.2@5929,2787.94 6011,2705.94 6011,2542.03 U13.1@6051.63,2501.4 6277.4,2501.4 P4.3@6315,2539
B0: U10.74 U23.11 | length 1720.6
  Top Layer w6: U23.11@2378,2992 2416.63,2992 2443.63,3019 2453.74,3019 2476,3041.26 2476,3043.32 2488.68,3056 2899,3056 2967,2988 2967,2708 2986,2689 2986,2441 3009.08,2417.92 U10.74@3497.33,2417.92
B0_N: COM2.3 R34.2 R35.1 U23.9 U26.1 | length 3063
  Top Layer w10: COM2.3@828,4287.91 918.43,4378.34 1357.44,4378.34 1454.07,4281.71 1454.07,4168.62 1472.69,4150 1574.61,4150 U26.1@1575.37,4149.24 1608,4149.24 1786,3971.24 1786,3608.14 1785,3607.14 1785,3527.72 1980.72,3332 2170.96,3332 2238,3264.96 2238,3162.72 2293.23,3107.48 2293.23,2965.23 2343.27,2915.19 2354.81,2915.19 U23.9@2378,2892 2411,2892 2487,2968 2559.06,2968 2604.06,2923 R34.2@2617.94,2923 R35.1@2717.06,2923
B0_P: COM2.7 R33.2 R34.1 U23.10 U26.2 | length 3063.5
  Top Layer w10: COM2.7@773.47,4176.09 777.57,4180.19 777.57,4308.8 807.11,4338.34 828.34,4338.34 888.34,4398.34 1365.72,4398.34 1484.06,4280 1517,4280 1572.95,4224.05 U26.2@1575.37,4224.05 1608,4224.05 1806,4026.05 1806,3599.85 1805,3598.85 1805,3536 1989,3352 2179.24,3352 2258,3273.24 2258,3171 2313.23,3115.77 2313.23,2995.23 2343.27,2965.19 2354.81,2965.19 U23.10@2378,2942 2405,2942 2476,3013 R33.2@2519.06,3013 R34.1@2617.94,3013
B1: U10.41 U29.13 | length 1682.9
  Top Layer w6: U29.13@2383.73,2616.81 2456.77,2616.81 2485.02,2588.56 2570.77,2588.56 2573.02,2590.81 v1(2868.81,2590.81) v1@2869,2591 ; v1(3605.6,2590.4) U10.41@3605.6,3038
  Bottom Layer w6: v1(2868.81,2590.81) 3605.81,2590.81 v1@3606,2591
B1_N: COM1.3 R43.2 R44.1 U29.15 U33.1 | length 2806.4
  Top Layer w10: COM1.3@826,3549 827,3548 COM1.3@827,3528.57 ; COM1.3@827,3549 856.88,3549 906.88,3599.01 948.66,3599.01 950.73,3601.08 951.99,3601.08 962.91,3612 1000.65,3612 1007.65,3619.01 1082.57,3619.01 1089.57,3612 1335.16,3612 1344.49,3602.67 1372.78,3602.67 1454.07,3521.37 1454.07,3492.56 1473.45,3473.19 U33.1@1575.37,3473.19 1608,3473.19 1640.93,3440.26 1640.93,3201.5 1682,3160.43 1682,2942 1697.93,2926.07 1697.93,2883.07 1741,2840 2246.57,2840 2308,2778.57 2308,2722.72 2315.72,2715 2381.92,2715 U29.15@2383.73,2716.81 2391.92,2725 2471,2725 2499.44,2696.56 2599.45,2696.56 2599.66,2696.35 2662.09,2696.35 2707.09,2741.35 R43.2@2731.01,2741.35 R44.1@2830.88,2741.35 ; R44.1@2830.23,2742.81 R44.1@2830.94,2742.1
B1_P: COM1.7 R42.2 R43.1 U29.14 U33.2 | length 2990.2
  Top Layer w10: COM1.7@772.47,3416.76 772.47,3545.37 806.11,3579.01 858.6,3579.01 898.6,3619.01 940.38,3619.01 942.45,3621.08 943.71,3621.08 954.63,3632 992.36,3632 999.37,3639.01 1090.85,3639.01 1097.86,3632 1343.44,3632 1352.78,3622.67 1381.06,3622.67 1455.74,3547.99 U33.2@1575.37,3547.99 1616.42,3547.99 1621.43,3553 1654.57,3553 1678,3529.57 1678,3492 1666,3480 1666,3204.72 1702,3168.72 1702,2950.28 1717.93,2934.35 1717.93,2891.35 1749.28,2860 2254.85,2860 2330,2784.85 2330,2749 v5@2329,2748 ; v5(2331,2691) 2355.19,2666.81 U29.14@2383.73,2666.81 2412.62,2666.81 2441.43,2638 2463,2638 2492.48,2608.52 2492.48,2606.56 2563.31,2606.56 2608.1,2651.35 R42.2@2630.88,2651.35 R43.1@2731.01,2651.35
  Bottom Layer w10: v5(2331,2691) v5(2331,2746)
B2: U10.116 U29.5 | length 2258.9
  Top Layer w6: U29.5@2167.23,2566.81 2175.94,2566.81 2233,2509.75 2233,2486.2 2385.2,2334 v1(2930.63,2334) ; v1(4078,2334) 4078,2216.65 4078.04,2216.6 U10.116@4078.04,2093.12
  Bottom Layer w6: v1(2930.63,2334) v1@4075,2334
B2_N: COM4.3 R52.2 R53.1 U29.7 U38.1 | length 1605.9
  Top Layer w10: COM4.3@827,2780.91 877.43,2831.34 886.88,2831.34 906.88,2851.34 948.66,2851.34 950.73,2853.41 951.99,2853.41 970.58,2872 1355.78,2872 1371.78,2856 1404.06,2856 1462.93,2797.13 U38.1@1575.37,2797.13 1575.87,2797.13 1689,2684 1689,2601.72 1777.29,2513.42 1777.29,2509.35 1786.08,2500.56 1873.16,2500.56 R52.2@1918.16,2455.56 2013.29,2455.56 R53.1@2015.29,2457.56 2024.54,2466.81 2082.24,2466.81 2082.43,2467 2115.57,2467 2115.76,2466.81 U29.7@2167.23,2466.81
B2_P: COM4.7 R51.2 R52.1 U29.6 U38.2 | length 1837.9
  Top Layer w10: COM4.7@776.57,2673.19 776.57,2801.8 806.11,2831.34 847.89,2831.34 848.52,2830.71 889.74,2871.93 940.97,2871.93 942.45,2873.41 943.71,2873.41 962.3,2892 1448.43,2892 1479.43,2923 1512.57,2923 1536,2899.57 1536,2877.93 1542,2871.93 U38.2@1575.37,2871.93 1575.37,2860.63 1709,2727 1709,2633.43 1773.44,2568.99 1773.44,2545.56 R51.2@1817.29,2545.56 R52.1@1918.16,2545.56 1941.08,2545.56 1984.08,2502.56 2046.5,2502.56 2060.75,2516.81 U29.6@2167.23,2516.81
B3: U10.101 U36.3 | length 2260.2
  Top Layer w6: U36.3@2170.99,2186 2236,2186 2289,2133 2289,1958 2336,1911 2432.26,1911 2451.26,1892 2482.74,1892 2496.74,1906 2822,1906 2943,2027 v1(2943,2244) ; U10.101@3782.77,2093.12 3783,2093.35 v1(3783,2244)
  Bottom Layer w6: v1(2943,2244) v1(3783,2244)
B3_N: COM3.3 R61.2 R62.1 U36.1 U42.1 | length 1558.5
  Top Layer w10: COM3.3@827,2033.24 827,2061 922,2156 1378.43,2156 1410.43,2124 1443.57,2124 1448.17,2128.6 U42.1@1572.37,2128.6 1627.4,2128.6 v5(1629,2127) ; v5@1629,2226 1769,2226 1780,2215 1872.06,2215 R61.2@1917.06,2260 2016.94,2260 2042.94,2286 U36.1@2167.23,2286 ; R62.1@2027.94,2260 R62.1@2028.94,2261
  Bottom Layer w10: v5(1629,2127) v5(1629,2227)
B3_P: COM3.7 R60.2 R61.1 U36.2 U42.2 | length 1628.6
  Top Layer w10: COM3.7@772.47,1921.43 772.47,2050.03 898.44,2176 1382.43,2176 1410.43,2204 1498.06,2204 1498.65,2203.4 U42.2@1572.37,2203.4 1757.6,2203.4 1791,2170 R60.2@1817.29,2170 R61.1@1917.06,2170 1940.72,2170 1984.72,2214 2145.23,2214 U36.2@2167.23,2236
B4: U10.88 U39.11 | length 1148.6
  Top Layer w6: U39.11@2387.5,1566 2432,1566 2464,1598 2476.74,1598 2527.74,1649 2905.37,1649 2964,1707.63 v1(2964,1962) ; U10.88@3497.33,2142.33 3539.67,2142.33 v1(3541,2141)
  Bottom Layer w6: v1(2964,1962) 2964,2059 3047.33,2142.33
B4_N: COM6.3 R70.2 R71.1 U25.1 U39.9 | length 2667.1
  Top Layer w10: COM6.3@827,1285.57 823,1289.57 823,1328 940.01,1445.01 1412.42,1445.01 1415.43,1442 1448.57,1442 1451.58,1445.01 U25.1@1575.37,1445.01 1629,1498.64 1629,1625.57 1683,1679.57 1683,1772 1753.81,1842.81 2228.19,1842.81 2249,1822 2249,1755.72 2313.29,1691.42 2313.29,1517.42 2343,1487.72 2343,1466 U39.9@2383.73,1466 ; U39.9@2387.5,1466 2410.69,1489.19 2437.19,1489.19 2487.25,1539.25 2580.75,1539.25 2625.75,1494.25 R70.2@2646.94,1494.25 R71.1@2747.06,1494.25
B4_P: COM6.7 R69.2 R70.1 U25.2 U39.10 | length 2649.2
  Top Layer w10: COM6.7@772.47,1173.76 772.47,1305.76 988.72,1522 1448.57,1522 1450.76,1519.81 U25.2@1575.37,1519.81 1609,1553.44 1609,1633.85 1663,1687.85 1663,1780.28 1745.53,1862.81 2236.47,1862.81 2269,1830.28 2269,1764 2333.29,1699.71 2333.29,1554.89 2343,1545.19 2343,1516 U39.10@2383.73,1516 ; U39.10@2387.5,1516 2429,1516 2497.25,1584.25 R69.2@2548.31,1584.25 R70.1@2646.94,1584.25
B5: U10.175 U43.13 | length 3904.6
  Top Layer w6: v1@4338,2929 4378.1,2969.1 U10.175@4442.21,2969.1
  Bottom Layer w6: U43.13@2182.5,1415 2173.79,1415 2134.07,1375.28 2134.07,1354.72 2148.6,1340.19 2539.19,1340.19 2572,1373 2572,1804.5 2691,1923.5 2691,2912 2699,2920 4329.35,2920 v1(4337,2927.65)
B5_N: COM5.3 R79.2 R80.1 U32.1 U43.15 | length 2829.8
  Top Layer w10: COM5.3@827,537.91 v5(827,628) 827,642 950,765 1453.57,765 1457.52,768.95 U32.1@1575.37,768.95
  Bottom Layer w10: v5@833,628 898.26,628 898.6,628.34 940.38,628.34 942.45,630.41 943.71,630.41 1000.3,687 1331,687 1680,1036 1680,1237.13 1722,1279.13 1722,1400.28 1814.72,1493 1900.94,1493 R79.2@1945.94,1538 R80.1@2046.06,1538 2159.5,1538 U43.15@2182.5,1515
B5_P: COM5.7 R78.2 R79.1 U32.2 U43.14 | length 3215.7
  Top Layer w10: COM5.7@772.47,426.09 772.47,615.76 1001.72,845 1453.57,845 1454.81,843.75 U32.2@1575.37,843.75
  Bottom Layer w10: COM5.7@772.47,426.09 776.57,430.19 776.57,558.8 806.11,588.34 886.88,588.34 906.88,608.34 948.66,608.34 950.73,610.41 951.99,610.41 1008.58,667 1339.28,667 1700,1027.72 1700,1228.85 1742,1270.85 1742,1392 1767.94,1417.94 1818,1417.94 R78.2@1848.06,1448 R79.1@1945.94,1448 1969.85,1448 2014.85,1493 2077.28,1493 2082.09,1488.19 2159.31,1488.19 U43.14@2182.5,1465
CAN1_H: P5.3 R28.2 U18.7 U19.1 | length 911.2
  Top Layer w10: U18.7@5705,2163 5736,2163 5957.06,1941.94 5957.06,1751 5995,1751 6002.6,1743.4 6057.63,1743.4 6095.23,1781 P5.3@6315,1781
CAN1_L: P5.4 R28.1 U18.6 U19.2 | length 955.9
  Top Layer w10: U18.6@5705,2113 5711,2107 5750,2107 5911,1946 5911,1716.06 5957.06,1670 5957.06,1661 5989,1661 5996.6,1668.6 6057.63,1668.6 6277.4,1668.6 P5.4@6315,1631
CAN1_RX: U10.11 U18.4 | length 2186.3
  Top Layer w6: v1@4196,2191 4196,3037.85 U10.11@4196.15,3038 ; v1@5396,2063 U18.4@5485,2063
  Bottom Layer w6: v1(4196,2190.65) 5209.92,2190.65 5279.06,2121.5 5337.14,2121.5 v1(5394,2064.65)
CAN1_TX: U10.128 U18.1 | length 1289
  Top Layer w6: v1(4314,2209.65) 4314.26,2209.39 U10.128@4314.26,2093.12 ; v1@5267,2213 U18.1@5485,2213
  Bottom Layer w6: v1@4314,2210 5213.19,2210 5213.54,2209.65 5264,2209.65 v1(5267,2212.65)
CAN2_H: P6.3 R29.2 U20.7 U21.1 | length 1000.3
  Top Layer w10: U20.7@5705,1571 5758,1571 5970.06,1358.94 5970.06,1073 6006,1073 6013.6,1065.4 6282.6,1065.4 P6.3@6315,1033
CAN2_L: P6.4 R29.1 U20.6 U21.2 | length 1069.7
  Top Layer w10: U20.6@5705,1521 5755,1521 5927,1349 5927,1031.06 5970.06,988 5970.06,983 6005,983 6012.6,990.6 6207.4,990.6 P6.4@6315,883
CAN2_RX: U10.92 U20.4 | length 2404.4
  Top Layer w6: v1@3605.6,1582.64 U10.92@3605.6,2093.12 ; v1(5300,1583) 5300,1579 5406,1473 U20.4@5453,1473
  Bottom Layer w6: v1@3606,1583 v1@5299,1583.98
  other v1: 3606,1582.64
CAN2_TX: U10.93 U20.1 | length 2297.5
  Top Layer w6: v1(3624,1625.64) 3625.28,1626.93 U10.93@3625.28,2093.12 ; v1(5382,1625.64) 5384.64,1623 U20.1@5453,1623
  Bottom Layer w6: v1(3624,1625.64) v1@5381.35,1625.64
COMP: C7.2 R2.2 U2.6 | length 239.8
  Bottom Layer w30: R2.2@5333,3631.06 5333,3735.94 C7.2@5333.06,3736 5350.06,3753 U2.6@5460.81,3753
DA_CLK: U10.51 U49.16 | length 1190.6
  Top Layer w6: v1(3063,3516) 3058,3511 3058,2855 3064.35,2848.65 3315,2848.65 3334,2867.65 3334,2870.68 U10.51@3497.33,2870.68
  Bottom Layer w6: v1(3063,3516) 3064,3517 U49.16@3137.24,3517
DA_CLR: U10.50 U49.9 | length 1476.5
  Top Layer w6: v1(3081,3848.65) 3081,3243 3076,3238 3076,2872 3082,2866 3280.28,2866 3304.64,2890.36 U10.50@3497.33,2890.36
  Bottom Layer w6: v1(3081,3848.65) 3098.35,3866 3136.24,3866 U49.9@3137.24,3867
DA_IN: U10.53 U49.15 | length 1281.9
  Top Layer w6: v1(3044,3565) 3039,3560 3039,2842 3048.35,2832.65 3495.99,2832.65 U10.53@3497.33,2831.31
  Bottom Layer w6: v1(3044,3565) 3046,3567 U49.15@3137.24,3567
DA_LDAC: U10.56 U49.1 | length 1314.1
  Top Layer w6: v1(3007,3516.65) 3007,3478.63 3020,3465.63 3020,2778 3025.75,2772.25 U10.56@3497.33,2772.25
  Bottom Layer w6: U49.1@2916.76,3517 3006.65,3517 v1(3007,3516.65)
DA_SYNC: U10.57 U49.2 | length 1380.9
  Top Layer w6: v1(2988,3566.65) 2988,3475 3004,3459 3004,2760.25 3008,2756.25 3493.65,2756.25 U10.57@3497.33,2752.57
  Bottom Layer w6: U49.2@2916.76,3567 2987.65,3567 v1(2988,3566.65)
DAC_REF: C70.2 C71.2 D8.2 R88.1 R89.1 R90.2 R97.1 R98.1 R105.1 R106.1 R113.1 R114.1 U49.8 | length 4508.2
  Top Layer w10: v1(1865,3574) 1866,3575 v1(1866,3934) v1(1866,4112) v1(1866,4649) v1@1866,4777 ; v1@2590,3600.65 v1(2590,4117.65) 2592.27,4115.37 2784.37,4115.37 2804.69,4095.05 2804.69,4076.31 D8.2@2820,4061
  Bottom Layer w10: R97.1@1820,3618.15 1820.85,3618.15 v1(1865,3574) ; R113.1@1820,3977.09 1822.91,3977.09 v1(1866,3934) ; R98.1@1820,4066.82 1820.82,4066.82 v1(1866,4112) ; R114.1@1820,4694.95 v1(1866,4649) ; v1@1866,4777 2428.16,4777 2510.21,4694.95 R106.1@2524,4694.95 2820,4398.95 D8.2@2820,4061 2820,4000.06 R90.2@2874,3946.06 ; R88.1@2524,3599.94 v1@2588.94,3599.94 ; R105.1@2524,3964.22 2574.78,3964.22 v1(2589,3950) 2593,3946 ; R89.1@2524,4329.58 2590,4263.58 v1(2590,4117.65) ; 2874,3909.76 R90.2@2874,3946.06 ; 2877.7,3906.06 U49.8@2916.76,3867 ; C71.2@2980,4043.94 C70.2@2980,3942.94 2877.13,3942.94 R90.2@2874,3946.06
  other v1: 2589,3599.65 1866,4778
FLASH_CLK: U10.132 U12.6 | length 638.2
  Top Layer w6: v1(4393,2044.65) U10.132@4393,2093.12 ; v1@4720.18,2044.82 4868,1897 U12.6@4868,1843
  Bottom Layer w6: v1@4393.35,2044.65 v1(4720,2044.65)
FLASH_CS: U10.131 U12.1 | length 727
  Top Layer w6: U10.131@4373.31,2093.12 4373.31,1893.68 4694,1573 U12.1@4768,1573
FLASH_MISO: U10.133 U12.2 | length 840.3
  Top Layer w6: U10.133@4442.21,2142.33 4489.67,2142.33 4511,2121 4511,1778.63 4655.63,1634 4805,1634 4818.06,1620.94 U12.2@4818.06,1573
FLASH_MOSI: U10.134 U12.5 | length 634.9
  Top Layer w8: U10.134@4442.21,2162.02 4644.98,2162.02 4918,1889 U12.5@4918,1843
